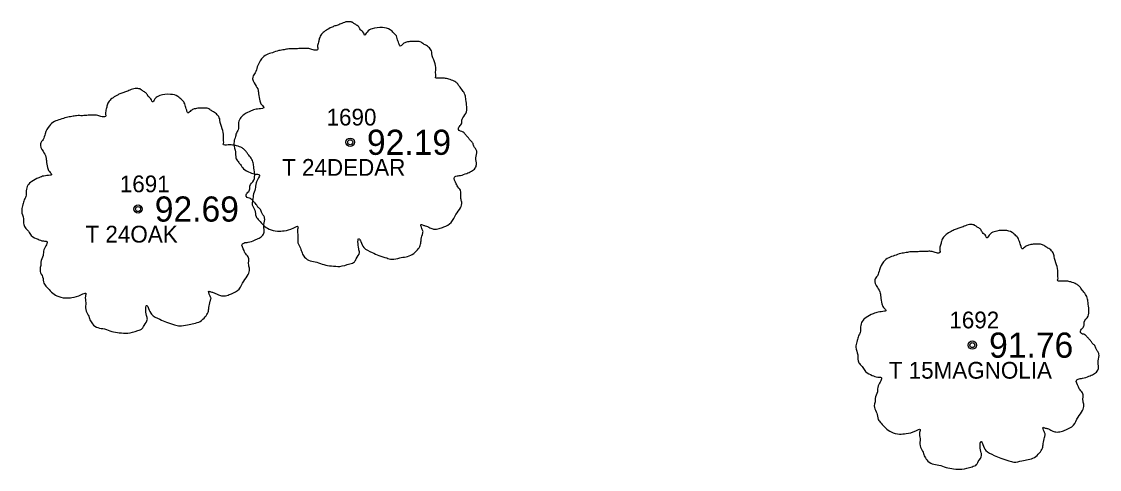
# Model space of a CAD drawing. Extents: x 2529517 to 2532038, y 935000 to 936944.
# Drawn here: x 2530967 to 2531031.3, y 935939 to 935965.8 of the extents above; entities that cross this region are included whole.
import ezdxf

# ---------------------------------------------------------------- set-up
doc = ezdxf.new("R2010")
doc.units = 0
for name, color, linetype in [('RD_EX_TX_VEG_ELEV', 7, 'Continuous'), ('RD_EX_VEG', 7, 'Continuous'), ('RD_EX_VEG_txCode', 7, 'Continuous'), ('RD_SMD_Locator', 7, 'Continuous')]:
    doc.layers.add(name, color=color, linetype=linetype)

msp = doc.modelspace()

# ---------------------------------------------------------------- linework, layer by layer
at = {"layer": 'RD_EX_VEG'}
for centre, radius in [((2530986.567, 935958.554), 0.25), ((2530986.555, 935958.535), 0.0001), ((2530973.91, 935954.571), 0.25), ((2530973.898, 935954.552), 0.0001), ((2531023.682, 935946.451), 0.25), ((2531023.669, 935946.432), 0.0001)]:
    msp.add_circle(centre, radius, dxfattribs=at)
for points in [[(2530986.699, 935965.721), (2530986.399, 935965.746), (2530986.075, 935965.646), (2530985.825, 935965.546), (2530985.6, 935965.471), (2530985.375, 935965.371), (2530985.075, 935965.196), (2530984.85, 935964.996), (2530984.725, 935964.746), (2530984.675, 935964.521), (2530984.625, 935964.246), (2530984.625, 935964.071), (2530984.5, 935964.046), (2530984.35, 935964.071), (2530984.1, 935964.146), (2530983.85, 935964.146), (2530983.601, 935964.146), (2530983.251, 935964.121), (2530982.901, 935964.121), (2530982.626, 935964.071), (2530982.301, 935964.022), (2530981.926, 935963.897), (2530981.576, 935963.772), (2530981.277, 935963.522), (2530981.027, 935963.047), (2530980.902, 935962.697), (2530980.752, 935962.447), (2530980.902, 935961.997), (2530981.077, 935961.648), (2530981.102, 935961.448), (2530981.177, 935961.023), (2530981.277, 935960.798), (2530981.402, 935960.598), (2530981.327, 935960.573), (2530980.952, 935960.523), (2530980.652, 935960.423), (2530980.227, 935960.198), (2530980.002, 935959.973), (2530979.902, 935959.648), (2530979.877, 935959.299), (2530979.777, 935959.099), (2530979.702, 935958.824), (2530979.677, 935958.749), (2530979.627, 935958.424), (2530979.727, 935957.974), (2530979.752, 935957.624), (2530979.877, 935957.399), (2530980.027, 935957.225), (2530980.202, 935956.975), (2530980.602, 935956.75), (2530980.927, 935956.65), (2530981.127, 935956.625), (2530980.952, 935956.125), (2530980.902, 935955.775), (2530980.777, 935955.375), (2530980.777, 935955.3), (2530980.727, 935954.826), (2530980.877, 935954.501), (2530980.952, 935954.126), (2530981.127, 935953.901), (2530981.402, 935953.601), (2530981.726, 935953.376), (2530982.226, 935953.251), (2530982.626, 935953.276), (2530983.201, 935953.451), (2530983.451, 935953.526), (2530983.426, 935953.351), (2530983.451, 935952.976), (2530983.451, 935952.552), (2530983.601, 935952.227), (2530983.701, 935951.952), (2530983.85, 935951.702), (2530984.175, 935951.477), (2530984.575, 935951.402), (2530985, 935951.252), (2530985.45, 935951.177), (2530985.95, 935951.152), (2530986.549, 935951.302), (2530986.824, 935951.427), (2530986.924, 935951.602), (2530987.124, 935951.977), (2530987.074, 935952.202), (2530987.099, 935952.801), (2530987.199, 935952.626), (2530987.374, 935952.277), (2530987.874, 935951.977), (2530988.274, 935951.802), (2530988.748, 935951.652), (2530989.048, 935951.577), (2530989.523, 935951.652), (2530989.898, 935951.727), (2530990.273, 935951.852), (2530990.573, 935952.127), (2530990.747, 935952.402), (2530990.797, 935952.676), (2530990.872, 935953.051), (2530990.922, 935953.226)], [(2530990.922, 935953.226), (2530990.847, 935953.401), (2530990.797, 935953.651), (2530990.872, 935953.626), (2530991.047, 935953.576), (2530991.322, 935953.451), (2530991.547, 935953.376), (2530991.872, 935953.401), (2530992.147, 935953.501), (2530992.597, 935953.776), (2530992.872, 935954.251), (2530993.146, 935954.651), (2530993.221, 935954.975), (2530993.171, 935955.2), (2530993.146, 935955.7), (2530992.946, 935955.95), (2530992.896, 935956.075), (2530992.797, 935956.475), (2530992.872, 935956.525), (2530993.146, 935956.575), (2530993.521, 935956.7), (2530993.796, 935956.825), (2530994.021, 935957), (2530994.096, 935957.225), (2530994.071, 935957.624), (2530994.121, 935958.024), (2530994.046, 935958.174), (2530993.946, 935958.324), (2530993.871, 935958.524), (2530993.721, 935958.674), (2530993.621, 935958.824), (2530993.521, 935958.924), (2530993.396, 935959.074), (2530993.221, 935959.199), (2530993.071, 935959.249), (2530993.021, 935959.399), (2530993.171, 935959.598), (2530993.221, 935959.698), (2530993.246, 935959.923), (2530993.471, 935960.273), (2530993.521, 935960.673), (2530993.471, 935961.098), (2530993.421, 935961.373), (2530993.271, 935961.648), (2530993.071, 935961.897), (2530992.946, 935962.072), (2530992.772, 935962.197), (2530992.447, 935962.322), (2530992.197, 935962.372), (2530991.847, 935962.372), (2530991.647, 935962.422), (2530991.672, 935962.472), (2530991.672, 935962.622), (2530991.672, 935962.897), (2530991.597, 935963.347), (2530991.447, 935963.847), (2530991.447, 935963.872), (2530991.347, 935964.121), (2530991.122, 935964.321), (2530990.947, 935964.421), (2530990.747, 935964.546), (2530990.498, 935964.571), (2530990.198, 935964.571), (2530989.923, 935964.521), (2530989.723, 935964.421), (2530989.548, 935964.296), (2530989.473, 935964.446), (2530989.373, 935964.746), (2530989.323, 935964.896), (2530989.173, 935965.071), (2530988.948, 935965.271), (2530988.498, 935965.396), (2530987.874, 935965.321), (2530987.574, 935965.121), (2530987.424, 935964.946), (2530987.374, 935965.071), (2530987.174, 935965.271), (2530987.074, 935965.446), (2530986.899, 935965.571), (2530986.749, 935965.671), (2530986.649, 935965.721)], [(2530974.042, 935961.738), (2530973.742, 935961.763), (2530973.418, 935961.663), (2530973.168, 935961.563), (2530972.943, 935961.488), (2530972.718, 935961.388), (2530972.418, 935961.213), (2530972.193, 935961.013), (2530972.068, 935960.764), (2530972.018, 935960.539), (2530971.968, 935960.264), (2530971.968, 935960.089), (2530971.843, 935960.064), (2530971.693, 935960.089), (2530971.443, 935960.164), (2530971.193, 935960.164), (2530970.944, 935960.164), (2530970.594, 935960.139), (2530970.244, 935960.139), (2530969.969, 935960.089), (2530969.644, 935960.039), (2530969.269, 935959.914), (2530968.919, 935959.789), (2530968.62, 935959.539), (2530968.37, 935959.064), (2530968.245, 935958.714), (2530968.095, 935958.465), (2530968.245, 935958.015), (2530968.42, 935957.665), (2530968.445, 935957.465), (2530968.52, 935957.04), (2530968.62, 935956.815), (2530968.745, 935956.615), (2530968.67, 935956.59), (2530968.295, 935956.54), (2530967.995, 935956.44), (2530967.57, 935956.216), (2530967.345, 935955.991), (2530967.245, 935955.666), (2530967.22, 935955.316), (2530967.12, 935955.116), (2530967.045, 935954.841), (2530967.02, 935954.766), (2530966.97, 935954.441), (2530967.07, 935953.991), (2530967.095, 935953.642), (2530967.22, 935953.417), (2530967.37, 935953.242), (2530967.545, 935952.992), (2530967.945, 935952.767), (2530968.27, 935952.667), (2530968.47, 935952.642), (2530968.295, 935952.142), (2530968.245, 935951.792), (2530968.12, 935951.393), (2530968.12, 935951.318), (2530968.07, 935950.843), (2530968.22, 935950.518), (2530968.295, 935950.143), (2530968.47, 935949.918), (2530968.745, 935949.618), (2530969.069, 935949.394), (2530969.569, 935949.269), (2530969.969, 935949.294), (2530970.544, 935949.468), (2530970.794, 935949.543), (2530970.769, 935949.369), (2530970.794, 935948.994), (2530970.794, 935948.569), (2530970.944, 935948.244), (2530971.044, 935947.969), (2530971.193, 935947.719), (2530971.518, 935947.494), (2530971.918, 935947.419), (2530972.343, 935947.269), (2530972.793, 935947.194), (2530973.293, 935947.169), (2530973.892, 935947.319), (2530974.167, 935947.444), (2530974.267, 935947.619), (2530974.467, 935947.994), (2530974.417, 935948.219), (2530974.442, 935948.819), (2530974.542, 935948.644), (2530974.717, 935948.294), (2530975.217, 935947.994), (2530975.617, 935947.819), (2530976.091, 935947.669), (2530976.391, 935947.594), (2530976.866, 935947.669), (2530977.241, 935947.744), (2530977.616, 935947.869), (2530977.916, 935948.144), (2530978.09, 935948.419), (2530978.14, 935948.694), (2530978.215, 935949.069), (2530978.265, 935949.244)], [(2530978.265, 935949.244), (2530978.19, 935949.419), (2530978.14, 935949.668), (2530978.215, 935949.643), (2530978.39, 935949.593), (2530978.665, 935949.468), (2530978.89, 935949.394), (2530979.215, 935949.419), (2530979.49, 935949.518), (2530979.94, 935949.793), (2530980.215, 935950.268), (2530980.489, 935950.668), (2530980.564, 935950.993), (2530980.514, 935951.218), (2530980.489, 935951.717), (2530980.289, 935951.967), (2530980.239, 935952.092), (2530980.14, 935952.492), (2530980.215, 935952.542), (2530980.489, 935952.592), (2530980.864, 935952.717), (2530981.139, 935952.842), (2530981.364, 935953.017), (2530981.439, 935953.242), (2530981.414, 935953.642), (2530981.464, 935954.041), (2530981.389, 935954.191), (2530981.289, 935954.341), (2530981.214, 935954.541), (2530981.064, 935954.691), (2530980.964, 935954.841), (2530980.864, 935954.941), (2530980.739, 935955.091), (2530980.564, 935955.216), (2530980.414, 935955.266), (2530980.364, 935955.416), (2530980.514, 935955.616), (2530980.564, 935955.716), (2530980.589, 935955.941), (2530980.814, 935956.29), (2530980.864, 935956.69), (2530980.814, 935957.115), (2530980.764, 935957.39), (2530980.614, 935957.665), (2530980.414, 935957.915), (2530980.289, 935958.09), (2530980.115, 935958.215), (2530979.79, 935958.34), (2530979.54, 935958.39), (2530979.19, 935958.39), (2530978.99, 935958.44), (2530979.015, 935958.49), (2530979.015, 935958.639), (2530979.015, 935958.914), (2530978.94, 935959.364), (2530978.79, 935959.864), (2530978.79, 935959.889), (2530978.69, 935960.139), (2530978.465, 935960.339), (2530978.29, 935960.439), (2530978.09, 935960.564), (2530977.841, 935960.589), (2530977.541, 935960.589), (2530977.266, 935960.539), (2530977.066, 935960.439), (2530976.891, 935960.314), (2530976.816, 935960.464), (2530976.716, 935960.764), (2530976.666, 935960.913), (2530976.516, 935961.088), (2530976.291, 935961.288), (2530975.841, 935961.413), (2530975.217, 935961.338), (2530974.917, 935961.138), (2530974.767, 935960.963), (2530974.717, 935961.088), (2530974.517, 935961.288), (2530974.417, 935961.463), (2530974.242, 935961.588), (2530974.092, 935961.688), (2530973.992, 935961.738)], [(2531023.813, 935953.618), (2531023.514, 935953.643), (2531023.189, 935953.543), (2531022.939, 935953.443), (2531022.714, 935953.368), (2531022.489, 935953.268), (2531022.189, 935953.093), (2531021.964, 935952.893), (2531021.839, 935952.643), (2531021.789, 935952.418), (2531021.739, 935952.144), (2531021.739, 935951.969), (2531021.614, 935951.944), (2531021.464, 935951.969), (2531021.215, 935952.044), (2531020.965, 935952.044), (2531020.715, 935952.044), (2531020.365, 935952.019), (2531020.015, 935952.019), (2531019.74, 935951.969), (2531019.415, 935951.919), (2531019.041, 935951.794), (2531018.691, 935951.669), (2531018.391, 935951.419), (2531018.141, 935950.944), (2531018.016, 935950.594), (2531017.866, 935950.344), (2531018.016, 935949.895), (2531018.191, 935949.545), (2531018.216, 935949.345), (2531018.291, 935948.92), (2531018.391, 935948.695), (2531018.516, 935948.495), (2531018.441, 935948.47), (2531018.066, 935948.42), (2531017.766, 935948.32), (2531017.341, 935948.095), (2531017.116, 935947.87), (2531017.016, 935947.545), (2531016.991, 935947.196), (2531016.892, 935946.996), (2531016.817, 935946.721), (2531016.792, 935946.646), (2531016.742, 935946.321), (2531016.842, 935945.871), (2531016.867, 935945.521), (2531016.991, 935945.296), (2531017.141, 935945.122), (2531017.316, 935944.872), (2531017.716, 935944.647), (2531018.041, 935944.547), (2531018.241, 935944.522), (2531018.066, 935944.022), (2531018.016, 935943.672), (2531017.891, 935943.272), (2531017.891, 935943.197), (2531017.841, 935942.723), (2531017.991, 935942.398), (2531018.066, 935942.023), (2531018.241, 935941.798), (2531018.516, 935941.498), (2531018.841, 935941.273), (2531019.34, 935941.148), (2531019.74, 935941.173), (2531020.315, 935941.348), (2531020.565, 935941.423), (2531020.54, 935941.248), (2531020.565, 935940.873), (2531020.565, 935940.449), (2531020.715, 935940.124), (2531020.815, 935939.849), (2531020.965, 935939.599), (2531021.29, 935939.374), (2531021.689, 935939.299), (2531022.114, 935939.149), (2531022.564, 935939.074), (2531023.064, 935939.049), (2531023.664, 935939.199), (2531023.938, 935939.324), (2531024.038, 935939.499), (2531024.238, 935939.874), (2531024.188, 935940.099), (2531024.213, 935940.699), (2531024.313, 935940.524), (2531024.488, 935940.174), (2531024.988, 935939.874), (2531025.388, 935939.699), (2531025.863, 935939.549), (2531026.162, 935939.474), (2531026.637, 935939.549), (2531027.012, 935939.624), (2531027.387, 935939.749), (2531027.687, 935940.024), (2531027.862, 935940.299), (2531027.912, 935940.574), (2531027.987, 935940.948), (2531028.037, 935941.123)], [(2531028.037, 935941.123), (2531027.962, 935941.298), (2531027.912, 935941.548), (2531027.987, 935941.523), (2531028.162, 935941.473), (2531028.436, 935941.348), (2531028.661, 935941.273), (2531028.986, 935941.298), (2531029.261, 935941.398), (2531029.711, 935941.673), (2531029.986, 935942.148), (2531030.261, 935942.548), (2531030.336, 935942.873), (2531030.286, 935943.097), (2531030.261, 935943.597), (2531030.061, 935943.847), (2531030.011, 935943.972), (2531029.911, 935944.372), (2531029.986, 935944.422), (2531030.261, 935944.472), (2531030.635, 935944.597), (2531030.91, 935944.722), (2531031.135, 935944.897), (2531031.21, 935945.122), (2531031.185, 935945.521), (2531031.235, 935945.921), (2531031.16, 935946.071), (2531031.06, 935946.221), (2531030.985, 935946.421), (2531030.835, 935946.571), (2531030.735, 935946.721), (2531030.635, 935946.821), (2531030.511, 935946.971), (2531030.336, 935947.096), (2531030.186, 935947.146), (2531030.136, 935947.296), (2531030.286, 935947.496), (2531030.336, 935947.595), (2531030.361, 935947.82), (2531030.586, 935948.17), (2531030.635, 935948.57), (2531030.586, 935948.995), (2531030.536, 935949.27), (2531030.386, 935949.545), (2531030.186, 935949.795), (2531030.061, 935949.969), (2531029.886, 935950.094), (2531029.561, 935950.219), (2531029.311, 935950.269), (2531028.961, 935950.269), (2531028.761, 935950.319), (2531028.786, 935950.369), (2531028.786, 935950.519), (2531028.786, 935950.794), (2531028.711, 935951.244), (2531028.561, 935951.744), (2531028.561, 935951.769), (2531028.461, 935952.019), (2531028.237, 935952.218), (2531028.062, 935952.318), (2531027.862, 935952.443), (2531027.612, 935952.468), (2531027.312, 935952.468), (2531027.037, 935952.418), (2531026.837, 935952.318), (2531026.662, 935952.193), (2531026.587, 935952.343), (2531026.487, 935952.643), (2531026.437, 935952.793), (2531026.287, 935952.968), (2531026.063, 935953.168), (2531025.613, 935953.293), (2531024.988, 935953.218), (2531024.688, 935953.018), (2531024.538, 935952.843), (2531024.488, 935952.968), (2531024.288, 935953.168), (2531024.188, 935953.343), (2531024.013, 935953.468), (2531023.863, 935953.568), (2531023.763, 935953.618)]]:
    msp.add_spline(points, degree=3, dxfattribs=at)
at = {"layer": 'RD_SMD_Locator'}
for centre in [(2530986.567, 935958.554), (2530973.91, 935954.571), (2531023.682, 935946.451)]:
    msp.add_circle(centre, 0.15, dxfattribs=at)

# ---------------------------------------------------------------- texts
at = {"layer": 'RD_EX_TX_VEG_ELEV'}
for s, p in [('92.19', (2530987.567, 935957.804)), ('92.69', (2530974.91, 935953.821)), ('91.76', (2531024.682, 935945.701))]:
    msp.add_text(s, height=1.5, dxfattribs=at).set_placement(p)
at = {"layer": 'RD_EX_VEG_txCode'}
for s, p in [('1690', (2530985.158, 935959.554)), ('T 24DEDAR', (2530982.504, 935956.554)), ('1691', (2530972.824, 935955.571)), ('T 24OAK', (2530970.776, 935952.571)), ('1692', (2531022.311, 935947.451)), ('T 15MAGNOLIA', (2531018.697, 935944.451))]:
    msp.add_text(s, height=1, dxfattribs=at).set_placement(p)

doc.saveas('drawing.dxf')
